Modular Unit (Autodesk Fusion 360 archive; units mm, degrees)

design "Modular Unit" references "Wing"
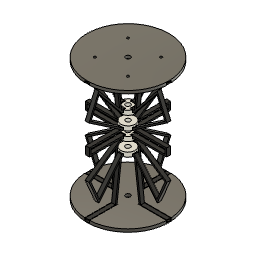
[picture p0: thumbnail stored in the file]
parameter "tendon_distance" = 12
parameter "tolerance" = 0.2
parameter "d90" = 360
parameter "d91" = 0
parameter "d92" = 0
parameter "d93" = 0.5
parameter "d94" = 0
parameter "d96" = 0.1
parameter "d97" = 3.5
parameter "d98" = 45
parameter "d99" = 1.5
parameter "d100" = 3.3
parameter "d101" = 8.5
parameter "d102" = 12.25
parameter "d104" = 360
parameter "d105" = -74
parameter "d106" = 0
parameter "d107" = 7.5
component_insert "Component Insert"
step "00000000-0000-0000-0000-000000000000" TotalAngle 360
work_plane "WorkPlane1" AlongDistance 0 Radius 0.15 AlongDistance 0 C-Pattern1-Angle 360 Diameter Dimension-2 3.5 Diameter Dimension-3 9 mirrorStitchTolerance 0.1
sketch "Sketch1" plane through (0, 2.4754, 0) normal (0, 1, 0) x axis (1, 0, 0)
  line L1 (-3.7331, 1) -> (-2.3956, 1)
  line L2 (-3.7331, -1) -> (-3.7331, 1)
  line L3 (-2.3956, -1) -> (-3.7331, -1)
  line L4 (-2.3956, 1) -> (-2.3956, -1)
  line L5 (-2.2456, -1.15) -> (-3.8831, -1.15)
  line L6 (-2.2456, 1.15) -> (-2.2456, -1.15)
  line L7 (-3.8831, 1.15) -> (-2.2456, 1.15)
  line L8 (-3.8831, -1.15) -> (-3.8831, 1.15)
  line L9 (-1.15, -3.8831) -> (-1.15, -2.2456)
  line L10 (-1.15, -2.2456) -> (1.15, -2.2456)
  line L11 (1.15, -2.2456) -> (1.15, -3.8831)
  line L12 (1.15, -3.8831) -> (-1.15, -3.8831)
  line L13 (3.8831, -1.15) -> (2.2456, -1.15)
  line L14 (2.2456, -1.15) -> (2.2456, 1.15)
  line L15 (2.2456, 1.15) -> (3.8831, 1.15)
  line L16 (3.8831, 1.15) -> (3.8831, -1.15)
  line L17 (1.15, 3.8831) -> (1.15, 2.2456)
  line L18 (1.15, 2.2456) -> (-1.15, 2.2456)
  line L19 (-1.15, 2.2456) -> (-1.15, 3.8831)
  line L20 (-1.15, 3.8831) -> (1.15, 3.8831)
  circle C1 centre (0, 0) radius 3.7331
  circle C2 centre (0, 0) radius 2.1956
  circle C3 centre (0, 0) radius 3.6331
  circle C4 centre (0, 0) radius 1.1956
  point P2 (0, 0)
  point P3 (0, 0)
  point P1 (0, 0)
  tangent C1 L2
  coincident P2 P3
  coincident P1 P2
  dimension "d160" = -0.1
  dimension "d161" = 0.15
  dimension "d162" = -1
  dimension "d163" diameter C4 = 2.3913
  dimension "d165" C-Pattern1-Angle = 360
extrude "Extrude1" new body sketch "Sketch1" profile of C3 L7 L6 L5 C4 L9 L10 L11 L13 L14 L15 L17 L18 L19 to an object
extrude "Extrude2" add sketch "Sketch1" profile of L1 L3 L4 C3 L7 L6 L5 C4 L9 L10 L11 L13 L14 L15 L17 L18 L19 along normal blind 1
extrude "Extrude5" sketch "Sketch1" profile of C3 L7 L6 L5 C4 L9 L10 L11 L13 L14 L15 L17 L18 L19 to an object
extrude "Extrude6" sketch "Sketch1" profile of L1 L3 L4 C3 L7 L6 L5 C4 L9 L10 L11 L13 L14 L15 L17 L18 L19 blind -1
mirror "Mirror3" mirrorStitchTolerance 0.1
work_plane "WorkPlane1" AlongDistance 0
sketch "Sketch1" plane through (0, 31, 0) normal (0, 1, 0) x axis (1, 0, 0)
  line L1 (-7.0508, 1) -> (-7.0508, -1)
  line L2 (-20.4, 1) -> (-7.0508, 1)
  line L3 (-20.4, -1) -> (-20.4, 1)
  line L4 (-7.0508, -1) -> (-20.4, -1)
  line L5 (-7.0508, -1) -> (-6.6508, -1)
  line L6 (-6.6508, 1) -> (-6.6508, -1)
  line L7 (-6.6508, 1) -> (-7.0508, 1)
  line L8 (-7.0508, -1) -> (-7.0508, 1)
  line L9 (-20.8, -1) -> (-20.4, -1)
  line L10 (-20.4, 1) -> (-20.4, -1)
  line L11 (-20.4, 1) -> (-20.8, 1)
  line L12 (-20.8, -1) -> (-20.8, 1)
  line L13 (-20.9952, -1) -> (-20.9952, 1)
  line L14 (-7.0501, -1.2) -> (-20.6, -1.2)
  line L15 (-7.0501, -1.2) -> (-6.4508, -1.2)
  line L16 (-6.4508, 1.2) -> (-6.4508, -1.2)
  line L17 (-6.4508, 1.2) -> (-7.0501, 1.2)
  line L18 (-20.6, 1.2) -> (-7.0501, 1.2)
  line L19 (-20.6, 1.2) -> (-20.9609, 1.2)
  line L20 (-20.6, -1.2) -> (-20.9609, -1.2)
  line L21 (1.2, -20.6) -> (1.2, -20.9609)
  line L22 (1.2, -7.0501) -> (1.2, -20.6)
  line L23 (1.2, -7.0501) -> (1.2, -6.4508)
  line L24 (-1.2, -6.4508) -> (1.2, -6.4508)
  line L25 (-1.2, -6.4508) -> (-1.2, -7.0501)
  line L26 (-1.2, -20.6) -> (-1.2, -7.0501)
  line L27 (-1.2, -20.6) -> (-1.2, -20.9609)
  line L28 (20.6, 1.2) -> (20.9609, 1.2)
  line L29 (7.0501, 1.2) -> (20.6, 1.2)
  line L30 (7.0501, 1.2) -> (6.4508, 1.2)
  line L31 (6.4508, -1.2) -> (6.4508, 1.2)
  line L32 (6.4508, -1.2) -> (7.0501, -1.2)
  line L33 (20.6, -1.2) -> (7.0501, -1.2)
  line L34 (20.6, -1.2) -> (20.9609, -1.2)
  line L35 (-1.2, 20.6) -> (-1.2, 20.9609)
  line L36 (-1.2, 7.0501) -> (-1.2, 20.6)
  line L37 (-1.2, 7.0501) -> (-1.2, 6.4508)
  line L38 (1.2, 6.4508) -> (-1.2, 6.4508)
  line L39 (1.2, 6.4508) -> (1.2, 7.0501)
  line L40 (1.2, 20.6) -> (1.2, 7.0501)
  line L41 (1.2, 20.6) -> (1.2, 20.9609)
  circle C1 centre (0, 0) radius 1.1956
  circle C2 centre (0, 0) radius 20.9952
  point P24 (-20.9609, 1.2)
  point P25 (-20.9609, -1.2)
  concentric C1 C2
  tangent C2 L13
  coincident C2 P24
  coincident C2 P25
  parallel L18 L19
  parallel L14 L20
  dimension "d169" = 0.2
  dimension "d186" C-Pattern1-Angle = 360
extrude "Extrude1" new body sketch "Sketch1" profile of C1 C2 L14 L15 L18 L16 L17 L19 L20 L21 L22 L23 L24 L25 L26 L27 L28 L29 L30 L31 L32 L33 L34 L35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 against normal blind 1
extrude "Extrude2" add sketch "Sketch1" profile of C1 C2 L14 L15 L18 L16 L17 L19 L20 L21 L22 L23 L24 L25 L26 L27 L28 L29 L30 L31 L32 L33 L34 L35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 along normal blind 0.5
sketch "Sketch2" plane through (0, 31.5, 0) normal (0, 1, 0) x axis (-1, 0, 0)
  line L1 (26.244, 0) -> (0, 0)
  line L2 (18.5573, 18.5573) -> (0, 0)
  circle C1 centre (0, 0) radius 1.1956
  circle C2 centre (0, 0) radius 20.9952
  circle C3 centre (8.4853, 8.4853) radius 0.6
  circle C4 centre (16.6128, 16.6128) radius 1.7
  circle C5 centre (16.6128, 16.6128) radius 2.75
  circle C6 centre (-8.4853, 8.4853) radius 0.6
  circle C7 centre (-16.6128, 16.6128) radius 1.7
  circle C8 centre (-8.4853, -8.4853) radius 0.6
  circle C9 centre (-16.6128, -16.6128) radius 1.7
  circle C10 centre (8.4853, -8.4853) radius 0.6
  circle C11 centre (16.6128, -16.6128) radius 1.7
  point P1 (0, 0)
  point P3 (0, 0)
  point P4 (26.244, 0)
  point P5 (0, 0)
  point P6 (18.5573, 18.5573)
  point P7 (8.4853, 8.4853)
  point P8 (16.6128, 16.6128)
  coincident P1 P3
  coincident C2 P4
  horizontal L1
  coincident P1 P5
  coincident C2 P6
  coincident L2 P7
  coincident L2 P8
  concentric C4 C5
  tangent C2 C5
  dimension "d187" angle L1 L2 = 45 (= "( 180 / number_of_wing ) * 1 deg")
  dimension "d188" diameter C5 = 5.5
  dimension "d189" diameter C4 = 3.4
  dimension "d190" diameter C3 = 1.2
  dimension "d191" distance P1 P7 = 12 (= "tendon_distance")
  dimension "d193" C-Pattern1-Angle = 360
mirror "Mirror1" mirrorStitchTolerance 0.1
extrude "Extrude4" cut sketch "Sketch2" profile of C3 C4 C6 C7 C8 C9 C10 C11 against normal blind 70
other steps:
create_component "CreateComponent3"
create_component "CreateComponent5"

design "Wing"
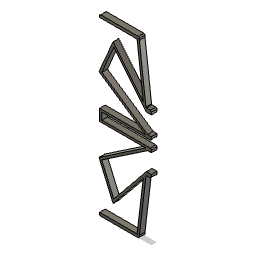
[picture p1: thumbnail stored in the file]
parameter "half_length" = 30 (= "1.5 * diameter / 2")
parameter "thickness" = 0.8
parameter "a1" = 12.5
parameter "a2" = 22
parameter "a3" = 34
parameter "a5" = 56
parameter "a6" = 57
parameter "a7" = 85
parameter "f1" = "1.05"
parameter "t2" = 3
parameter "width" = 2
parameter "diameter" = 40
parameter "d147" = 1
parameter "d160" = 1
parameter "d166" = 1.25
sketch "Sketch1" plane through (0, 0, 0) normal (0, 0, 1) x axis (1, 0, 0)
  line L1 (-20.8, 30) -> (0, 30)
  line L2 (0, 30) -> (0, 0)
  line L3 (0, 0) -> (-20, 0)
  line L4 (-20, 13.4902) -> (0, 0)
  line L5 (-6.6508, 30) -> (0, 0)
  line L6 (-20.8, 31) -> (-20.8, 30)
  line L7 (0, 31) -> (-20.8, 31)
  line L8 (0, 30) -> (0, 31)
  line L9 (-3.2591, 8.0665) -> (0, 0)
  line L10 (-15.7692, 23.3789) -> (0, 0)
  line L11 (-1.887, 1.2254) -> (0, 0)
  line L12 (-20, 1.2254) -> (-20, 0)
  line L13 (-1.887, 1.2254) -> (-20, 1.2254)
  line L14 (-20, 13.4902) -> (-1.887, 1.2254)
  line L15 (-15.7692, 23.3789) -> (-20, 13.4902)
  line L16 (-3.2591, 8.0665) -> (-15.7692, 23.3789)
  line L17 (-6.6508, 30) -> (-1.883, 8.4938)
  line L18 (-20, 0) -> (-20.8, 0)
  line L19 (-20.8, 2.0254) -> (-20.8, 0)
  line L20 (-4.4953, 2.0254) -> (-20.8, 2.0254)
  line L21 (-20.9952, 13.1979) -> (-4.4953, 2.0254)
  line L22 (-15.9853, 24.9077) -> (-20.9952, 13.1979)
  line L23 (-2.4548, 8.3465) -> (-15.9853, 24.9077)
  line L24 (-6.6508, 31) -> (-6.6508, 30)
  line L25 (-3.9809, 7.7358) -> (-6.6508, 30)
  line L26 (-5.2736, 11.7967) -> (-7.4566, 30)
  circle C1 centre (0, 0) radius 2.25
  circle C2 centre (0, 0) radius 3.61
  circle C3 centre (0, 0) radius 8.7
  circle C4 centre (0, 0) radius 10.06
  arc A1 centre (0, 0) radius 8.7 clockwise from (-3.2591, 8.0665) to (-3.9809, 7.7358)
  point P1 (0, 0)
  point P2 (0, 30)
  point P4 (0, 0)
  point P6 (0, 0)
  point P7 (0, 0)
  point P9 (0, 0)
  point P10 (-6.6508, 30)
  point P13 (-1.883, 8.4938)
  point P14 (-6.6508, 30)
  point P15 (0, 0)
  point P17 (-3.2591, 8.0665)
  point P18 (0, 0)
  point P16 (-3.2591, 8.0665)
  point P20 (0, 0)
  point P22 (-3.2591, 8.0665)
  point P23 (-1.883, 8.4938)
  point P24 (-6.6508, 30)
  point P25 (-20, 0)
  point P26 (-20, 0)
  point P3 (-20.8, 30)
  point P28 (-20.8, 2.0254)
  point P5 (-20, 1.2254)
  point P8 (-20, 13.4902)
  point P32 (0, 0)
  point P21 (-1.887, 1.2254)
  point P34 (0, 0)
  point P36 (-2.4548, 8.3465)
  point P37 (-6.6508, 30)
  point P38 (-6.6508, 31)
  point P39 (-6.6508, 30)
  point P41 (-7.4566, 30)
  point P42 (-5.2736, 11.7967)
  point P44 (-3.9809, 7.7358)
  point P45 (-3.2591, 8.0665)
  point P43 (0, 0)
  point P40 (-3.9809, 7.7358)
  point P11 (-20.8, 31)
  point P19 (-15.7692, 23.3789)
  horizontal L1
  vertical P1 P2
  coincident P1 P4
  coincident P1 P6
  perpendicular L2 L3
  coincident P1 P7
  coincident P1 P9
  perpendicular L1 L6
  horizontal L7
  perpendicular L1 L8
  coincident L1 P10
  coincident L5 P13
  coincident P10 P14
  coincident P1 P15
  coincident L9 P17
  coincident P1 P18
  coincident P16 P17
  coincident P1 P20
  coincident P17 P22
  coincident P13 P23
  coincident P14 P24
  vertical L12
  coincident P25 P26
  horizontal L13
  vertical P3 P28
  perpendicular L12 L18
  vertical P5 P8
  coincident P1 P32
  coincident P21 C1
  coincident P4 P34
  coincident P13 C3
  coincident C3 P36
  coincident L1 P37
  coincident L7 P38
  perpendicular L7 L24
  coincident P14 L24
  coincident P14 P39
  coincident L1 P41
  coincident L23 P42
  parallel L25 L26
  coincident L25 P44
  coincident P17 P45
  coincident P32 P43
  coincident C3 P40
  dimension "d40" distance P1 P2 = 30 (= "half_length")
  dimension "d45" angle L2 L4 = 56 (= "a5")
  dimension "d47" angle L2 L5 = 12.5 (= "a1")
  dimension "d57" distance P3 P11 = 1
  dimension "d66" distance P1 P13 = 8.7 (= "f2 * half_length")
  dimension "d67" angle L2 L9 = 22 (= "a2")
  dimension "d68" distance P1 P17 = 8.7 (= "f2 * half_length")
  dimension "d69" angle L2 L10 = 34 (= "a3")
  dimension "d70" distance P1 P19 = 28.2 (= "f3 * half_length")
  dimension "d72" angle L2 L11 = 57 (= "a6")
  dimension "d73" distance P1 P21 = 2.25 (= "f7 * half_length / 2")
  dimension "d86" distance P6 P25 = 20 (= "diameter / 2")
  dimension "d88" = 1.36 (= "thickness * 1.7")
  dimension "d89" = 1.36 (= "d88")
  dimension "d142" distance L16 L23 = 0.8 (= "thickness")
  dimension "d143" distance L14 L21 = 0.8 (= "thickness")
  dimension "d144" distance L15 L22 = 0.8 (= "thickness")
  dimension "d145" distance L13 L20 = 0.8 (= "thickness")
  dimension "d146" distance L12 L19 = 0.8 (= "thickness")
  dimension "d157" distance L2 P40 = 3.9809 (= "( 2.5 * 10 / ( 2 * 3.14 ) ) * 1 mm")
  dimension "d159" distance L25 L26 = 0.8 (= "thickness")
  dimension "d102" distance = 1.5
  dimension "d103" Side1Offset = 0
  dimension "d104" TaperAngle = 0
  dimension "d105" distance = 1.7
  dimension "d106" distance = 1
  dimension "d107" distance = 1 (= "d106")
  dimension "d108" Side1Offset = 0
  dimension "d109" TaperAngle = 0
  dimension "d110" distance = 1
  dimension "d111" distance = 1
  dimension "d114" Radius = 0.2
  dimension "d115" distance = 1.5
  dimension "d116" AlongDistance = -2
  dimension "d117" TaperAngle = 0
  dimension "d118" AlongDistance = -18
  dimension "d119" TaperAngle = 0
  dimension "d121" TaperAngle = 0
  dimension "d122" distance = 2.75
  dimension "d123" Side1Offset = 0
  dimension "d125" Radius = 0.5
  dimension "d127" distance = 2.75
  dimension "d128" distance = 1
  dimension "d130" Radius = 0.5
  dimension "d132" AlongDistance = -2
  dimension "d133" TaperAngle = 0
  dimension "d134" Side1Offset = 0
  dimension "d135" TaperAngle = 0
  dimension "d137" Radius = 0.25
  dimension "d139" Radius = 0.25
  dimension "d140" distance = 1 (= "thickness")
  dimension "d141" distance = 1.4073
extrude "Extrude1" new body sketch "Sketch1" profile of L1 L6 L7 L12 L13 L14 L15 L16 L22 L23 L21 L20 L19 L18 C2 C4 L24 L25 L26 distance 1 (= "width / 2")
fillet "Fillet3" radius 0.25
fillet "Fillet4" radius 1
fillet "Fillet5" radius 0.25
sketch "Sketch7" plane through (0, 0, 1) normal (0, 0, 1) x axis (1, 0, 0)
  line L1 (-15.9853, 24.9077) -> (-5.2736, 11.7967)
  line L2 (-20.9952, 13.1979) -> (-15.9853, 24.9077)
  line L3 (-4.4953, 2.0254) -> (-20.9952, 13.1979)
  line L4 (-20, 13.4902) -> (-3.0133, 1.9881)
  line L5 (-15.7692, 23.3789) -> (-20, 13.4902)
  line L6 (-4.1543, 9.1622) -> (-15.7692, 23.3789)
  line L7 (-7.4566, 30) -> (-20.8, 30)
  line L8 (-5.2736, 11.7967) -> (-7.4566, 30)
  line L9 (-6.6508, 30) -> (-4.3293, 10.6409)
  line L10 (-6.6508, 31) -> (-6.6508, 30)
  line L11 (-20.8, 31) -> (-6.6508, 31)
  line L12 (-20.8, 30) -> (-20.8, 31)
  line L13 (-20.8, 2.0254) -> (-4.4953, 2.0254)
  line L14 (-20.8, 0) -> (-20.8, 2.0254)
  line L15 (-20, 0) -> (-20.8, 0)
  line L16 (-20, 1.2254) -> (-20, 0)
  line L17 (-3.3956, 1.2254) -> (-20, 1.2254)
  line L18 (-2.3956, 1.2254) -> (-3.3956, 1.2254)
  line L19 (-2.3956, 2.4754) -> (-2.3956, 1.2254)
  line L20 (-3.7331, 2.4754) -> (-2.3956, 2.4754)
  line L21 (-2.3956, 9.1622) -> (-4.1543, 9.1622)
  line L22 (-2.3956, 10.4122) -> (-2.3956, 9.1622)
  line L23 (-5.1755, 10.4122) -> (-2.3956, 10.4122)
  line L24 (-4.3293, 10.6409) -> (-3.3776, 9.476)
  arc A1 centre (0, 0) radius 3.61 clockwise from (-3.3956, 1.2254) to (-3.0133, 1.9881)
  arc A2 centre (0, 0) radius 10.06 clockwise from (-4.1543, 9.1622) to (-3.3776, 9.476)
  point P22 (-3.3956, 1.2254)
  point P24 (-3.3956, 1.2254)
  point P27 (-3.7331, 2.4754)
  point P17 (-4.1543, 9.1622)
  point P28 (-4.1543, 9.1622)
  point P31 (-5.1755, 10.4122)
  point P26 (-2.3956, 2.4754)
  point P29 (-2.3956, 9.1622)
  point P25 (-2.3956, 1.2254)
  point P30 (-2.3956, 10.4122)
  coincident P22 P24
  horizontal L18
  perpendicular L18 L19
  coincident L4 P27
  perpendicular L19 L20
  coincident P17 P28
  horizontal L21
  perpendicular L21 L22
  coincident L6 P31
  perpendicular L22 L23
  vertical P26 P29
  dimension "d169" distance P25 P26 = 1.25
  dimension "d170" distance P24 P25 = 1
  dimension "d171" distance P29 P30 = 1.25 (= "d169")
extrude "Extrude9" add sketch "Sketch7" profile of L1 L2 L3 L4 L5 L6 L7 L8 L9 L10 L11 L12 L13 L14 L15 L16 L17 A1 L18 L19 L20 L21 L22 L23 to an object
fillet "Fillet11" radius 0.4
mirror "Mirror3" mirrorStitchTolerance 0.1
